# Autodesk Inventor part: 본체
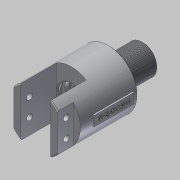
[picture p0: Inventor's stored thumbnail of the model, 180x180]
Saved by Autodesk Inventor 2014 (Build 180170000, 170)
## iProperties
Created: 2019-02
Part Number: 본체
Material: 알루미늄 6061
Document SubType Name: Modeling
Designer: 602-10
Density: 2.71 g/cm^3
Appearance: 알루미늄 - 평지
Mass: 347.17 g
Surface Area: 290.427 cm^2
Volume: 128.107 cm^3
Author: 602-10
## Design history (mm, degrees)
sketch "스케치1"
  geometry: C1 r 29 at (0, 0); 1 further point
  constraints: 1 centre point, 1 coincident
  dimensions: "d0" = 58 diameter of C1
extrude "돌출1" new body sketch "스케치1" distance "d1" = 74; taper "d2" = 0 deg
sketch "스케치2"
  geometry: L1 (15, 74)-(-15, 74); L2 (-15, 74)-(-15, 38); L3 (-15, 38)-(15, 38); L4 (15, 38)-(15, 74); L5 (29, 74)-(-29, 74) reference; 2 further points
  constraints: 8 end point, 2 midpoint, 2 parallel, 1 horizontal, 1 perpendicular
  dimensions: "d3" = 30 distance of L1.start L1.end; "d4" = 36 distance of L3.end L1.start
extrude "돌출2" cut sketch "스케치2" stored distance "d5" = 10; taper "d6" = 0 deg
sketch "스케치3"
  geometry: L1 (-22, 74)-(22, 74); L2 (29, 74)-(15, 74) reference; L3 (22, 74)-(22, 58); L4 (22, 58)-(35.26, 58); L5 (35.26, 58)-(35.26, 83.924); L6 (35.26, 83.924)-(-35.662, 83.924); L7 (-22, 74)-(-22, 58); L8 (-22, 58)-(-37.539, 58); L9 (-37.539, 58)-(-38.343, 84.862); L10 (-38.343, 84.862)-(-35.662, 83.924); 2 further points
  constraints: 18 end point, 4 perpendicular, 2 parallel, 1 horizontal, 1 horizontal alignment, 1 midpoint, 1 vertical alignment
  dimensions: "d7" = 44 distance of L1.start L1.end; "d8" = 16 distance of L1.end L3.end; "d9" = 16 distance of L1.start L7.end
extrude "돌출3" cut sketch "스케치3" stored distance "d10" = 0; taper "d11" = 0 deg
sketch "스케치4"
  geometry: L1 (-29, 38)-(29, 38) reference; L2 (29, 38)-(29, 0) reference; L3 (29, 0)-(-29, 0) reference; L4 (-29, 0)-(-29, 38) reference; L5 (0, 0)-(0, 38); L6 (-24.819, 38)-(24.819, 38) reference; L7 (14, 38)-(14, 35.35); L8 (14, 35.35)-(17, 35.35); L9 (17, 35.35)-(17, 30.65); L10 (14, 30.65)-(14, 26.35); L11 (14, 26.35)-(17, 26.35); L12 (17, 26.35)-(17, 21.65); L13 (17, 21.65)-(14, 21.65); L14 (14, 21.65)-(14, 18); L15 (14, 18)-(16, 18); L16 (16, 18)-(16, 11); L17 (16, 11)-(4, 11); L18 (4, 11)-(4, 0); L19 (14, 30.65)-(17, 30.65); L20 (0, 0)-(4, 0); L21 (14, 38)-(0, 38); 2 further points
  constraints: 32 end point, 10 parallel, 4 perpendicular, 3 midpoint, 2 collinear, 2 point on line
  dimensions: "d12" = 34 diameter of L9 L5; "d13" = 34 diameter of L12 L5; "d14" = 32 diameter of L16 L5; "d15" = 28 diameter of L14 L5; "d16" = 28 diameter of L10 L5; "d17" = 28 diameter of L7 L5; "d18" = 5 distance from line of L1 point (17, 33); "d19" = 4.7 distance of L8.end L9.end; "d20" = 9 distance of point (17, 33) point (17, 24); "d21" = 4.7 distance of L11.end L12.end; "d22" = 7 distance of L15.end L16.end; "d23" = 27 distance between parallel lines of L1 L17; "d24" = 20 distance between parallel lines of L6 L15 (derived); "d25" = 8 diameter of L18 L5
revolve "회전1" sketch "스케치4" stored, may be unused: angle "d26" = 90 deg
sketch "스케치5"
  geometry: C1 r 13 at (0, 0); 1 further point
  constraints: 1 centre point, 1 coincident
  dimensions: "d27" = 26 diameter of C1
extrude "돌출4" join sketch "스케치5" distance "d28" = 5; taper "d29" = 0 deg
sketch "스케치6"
  geometry: C1 r 15 at (0, 0); 1 further point
  constraints: 1 centre point, 1 coincident
  dimensions: "d30" = 30 diameter of C1
extrude "돌출5" join sketch "스케치6" distance "d31" = 29; taper "d32" = 0 deg
hole "구멍1" diameter "d35" = 12.376; stored, may be unused: countersink angle "d39" = 90 deg, drill point angle "d41" = 118 deg; dims "d33" = 10, "d34" = 10, "d36" = 18, "d37" = 4, "d38" = 2, "d40" = 22
sketch "스케치7"
  geometry: C1 r 4 at (0, 0) reference; 1 further point
extrude "돌출6" cut sketch "스케치7" distance "d42" = 34; taper "d43" = 0 deg
chamfer "모따기1" distance "d44" = 1; stored, may be unused: second distance "d45" = 2, angle "d46" = 45 deg
feature "스레드1" dims "d47" = 10, "d48" = 0
chamfer "모따기2" distance "d49" = 1; stored, may be unused: second distance "d50" = 2, angle "d51" = 45 deg
fillet "모깎기1" dims "d52" = 0.8
sketch "스케치8"
  geometry: L1 (-16, 42.538)-(-16, -4.749) reference; 3 further points
  constraints: 1 vertical alignment
  dimensions: "d53" = 9 vertical distance of point (58, 18.894) point (-7, 9.894); "d54" = 9 distance from line of L1 point (-7, 9.894); "d55" = 18 distance of point (-7, 9.894) point (-7, 27.894)
hole "구멍2" sketch "스케치8" at (-7, 27.894), (-7, 9.894) diameter "d56" = 6; stored, may be unused: countersink angle "d60" = 90 deg, drill point angle "d62" = 118 deg; dims "d57" = 18, "d58" = 4, "d59" = 2, "d61" = 22
node "작업 평면1"
sketch "스케치9"
  geometry: L1 (-5, 5)-(5, 5); L2 (5, 5)-(5, 45); L3 (5, 45)-(-5, 45); L4 (-5, 45)-(-5, 5); L5 (28, 0)-(-28, 0) reference; 2 further points
  constraints: 8 end point, 2 parallel, 1 horizontal, 1 midpoint, 1 perpendicular, 1 vertical alignment
  dimensions: "d64" = 40 distance of L1.end L2.end; "d65" = 10 distance of L2.end L3.end; "d66" = 5 distance between parallel lines of L5 L1
extrude "돌출7" join sketch "스케치9" stored distance "d67" = 34; taper "d68" = 0 deg
sketch "스케치10"
  geometry: L1 (-5, -5)-(-5, 5) reference; 2 further points
  constraints: 1 horizontal alignment, 1 other
  dimensions: "d69" = 20 distance from line of L1 point (-25, 0)
feature "엠보싱1" sketch "스케치10" dims "d70" = 0.5, "d71" = 0
node "솔리드1"
node "절단 모서리 투영1"
